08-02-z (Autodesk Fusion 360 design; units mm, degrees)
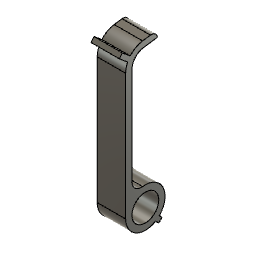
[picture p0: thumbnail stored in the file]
sketch "スケッチ1" plane through (0, 0, 0) normal (1, 0, 0) x axis (0, 0, -1)
  circle C1 centre (0, 0) radius 6.25
  point P1 (0, 0)
  point P2 (0, 0)
  coincident P1 P2
  dimension "d1" diameter C1 = 12.5
extrude "押し出し1" new body sketch "スケッチ1" distance 9
sketch "スケッチ2" plane through (0, 0, 0) normal (1, 0, 0) x axis (0, 0, -1)
  line L1 (-4.25, 0) -> (-6.25, 0)
  line L2 (-4.25, 40) -> (-4.25, 0)
  line L3 (3.8647, 44.8349) -> (-0.5915, 44.2086)
  line L4 (3.5864, 46.8155) -> (3.8647, 44.8349)
  line L5 (-0.8698, 46.1892) -> (3.5864, 46.8155)
  line L6 (-6.25, 0) -> (-6.25, 40)
  circle C1 centre (0, 0) radius 6.25
  arc A1 centre (0, 40) radius 4.25 clockwise from (-4.25, 40) to (-0.5915, 44.2086)
  arc A2 centre (0, 40) radius 6.25 clockwise from (-6.25, 40) to (-0.8698, 46.1892)
  point P1 (0, 0)
  point P9 (0, 40)
  point P12 (0, 40)
  horizontal L1
  vertical L6
  vertical L2
  parallel L3 L5
  perpendicular L4 L5
  coincident P1 L1
  tangent L6 C1
  tangent L2 A1
  tangent L3 A1
  tangent L5 A2
  tangent L6 A2
  dimension "d4" distance L2 L6 = 2
  dimension "d5" distance L3 L5 = 2
  dimension "d6" angle L2 L3 = 98
  dimension "d7" radius A1 = 4.25
  dimension "d8" radius A2 = 6.25
  dimension "d9" distance L4 P9 = 4.5
  dimension "d10" distance P1 P12 = 40
extrude "押し出し2" add sketch "スケッチ2" profile of L2 L3 L4 L5 L6 C1 A1 A2 distance 9
fillet "フィレット1" radius 2
fillet "フィレット2" radius 3
sketch "スケッチ3" plane through (0, 0, 0) normal (1, 0, 0) x axis (0, 0, -1)
  line L1 (5.3033, -5.3033) -> (0, 0)
  line L2 (4.2426, -6.364) -> (5.3033, -5.3033)
  line L3 (-1.0607, -1.0607) -> (4.2426, -6.364)
  line L4 (0, 0) -> (-1.0607, -1.0607)
  line L5 (-22.5, 0) -> (-1.75, 0)
  point P1 (0, 0)
  point P2 (0, 0)
  point P4 (4.2426, -6.364)
  point P5 (-1.0607, -1.0607)
  perpendicular L1 L2
  parallel L1 L3
  parallel L2 L4
  coincident P1 P2
  dimension "d20" angle L1 L5 = 45
  dimension "d21" distance P4 P5 = 7.5
  dimension "d22" distance L1 L3 = 1.5
extrude "押し出し3" add sketch "スケッチ3" profile of L1 L2 L3 L4 distance 9
sketch "スケッチ4" plane through (0, 0, 0) normal (1, 0, 0) x axis (0, 0, -1)
  line L1 (-7.2774, 46.1065) -> (0, 40)
  line L2 (-8.2416, 44.9574) -> (-7.2774, 46.1065)
  line L3 (-0.9642, 38.8509) -> (-8.2416, 44.9574)
  line L4 (0, 40) -> (-0.9642, 38.8509)
  line L5 (0, 22.5) -> (0, 1.75)
  arc A1 centre (0, 40) radius 4.25 clockwise from (-4.25, 40) to (-0.5915, 44.2086)
  point P4 (0, 40)
  point P5 (0, 40)
  perpendicular L1 L2
  parallel L1 L3
  parallel L2 L4
  coincident P4 P5
  dimension "d28" angle L1 L5 = 50
  dimension "d29" distance L1 L3 = 1.5
  dimension "d30" distance L2 L4 = 9.5
extrude "押し出し4" add sketch "スケッチ4" profile of A1 L1 L2 L3 distance 9
sketch "スケッチ5" plane through (0, 43.4339, 6.1042) normal (0, -0.9903, -0.1392) x axis (-1, 0, 0)
  line L1 (-4.5, 10.0669) -> (4.5, 10.0669)
  line L2 (-4.5, 5.5669) -> (-4.5, 10.0669)
  line L3 (4.5, 5.5669) -> (-4.5, 5.5669)
  line L4 (4.5, 10.0669) -> (4.5, 5.5669)
  circle C1 centre (0, 8.0669) radius 0.75
  point P1 (0, 0)
  point P6 (0, 8.0669)
  vertical P1 P6
  dimension "d33" distance L1 P6 = 2
  dimension "d34" diameter C1 = 1.5
extrude "押し出し5" add sketch "スケッチ5" profile of C1 along normal blind 0.7
fillet "フィレット3" radius 0.6
hole "穴" HoleDepth 9 HoleDiameter 8.5 TipAngle 118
